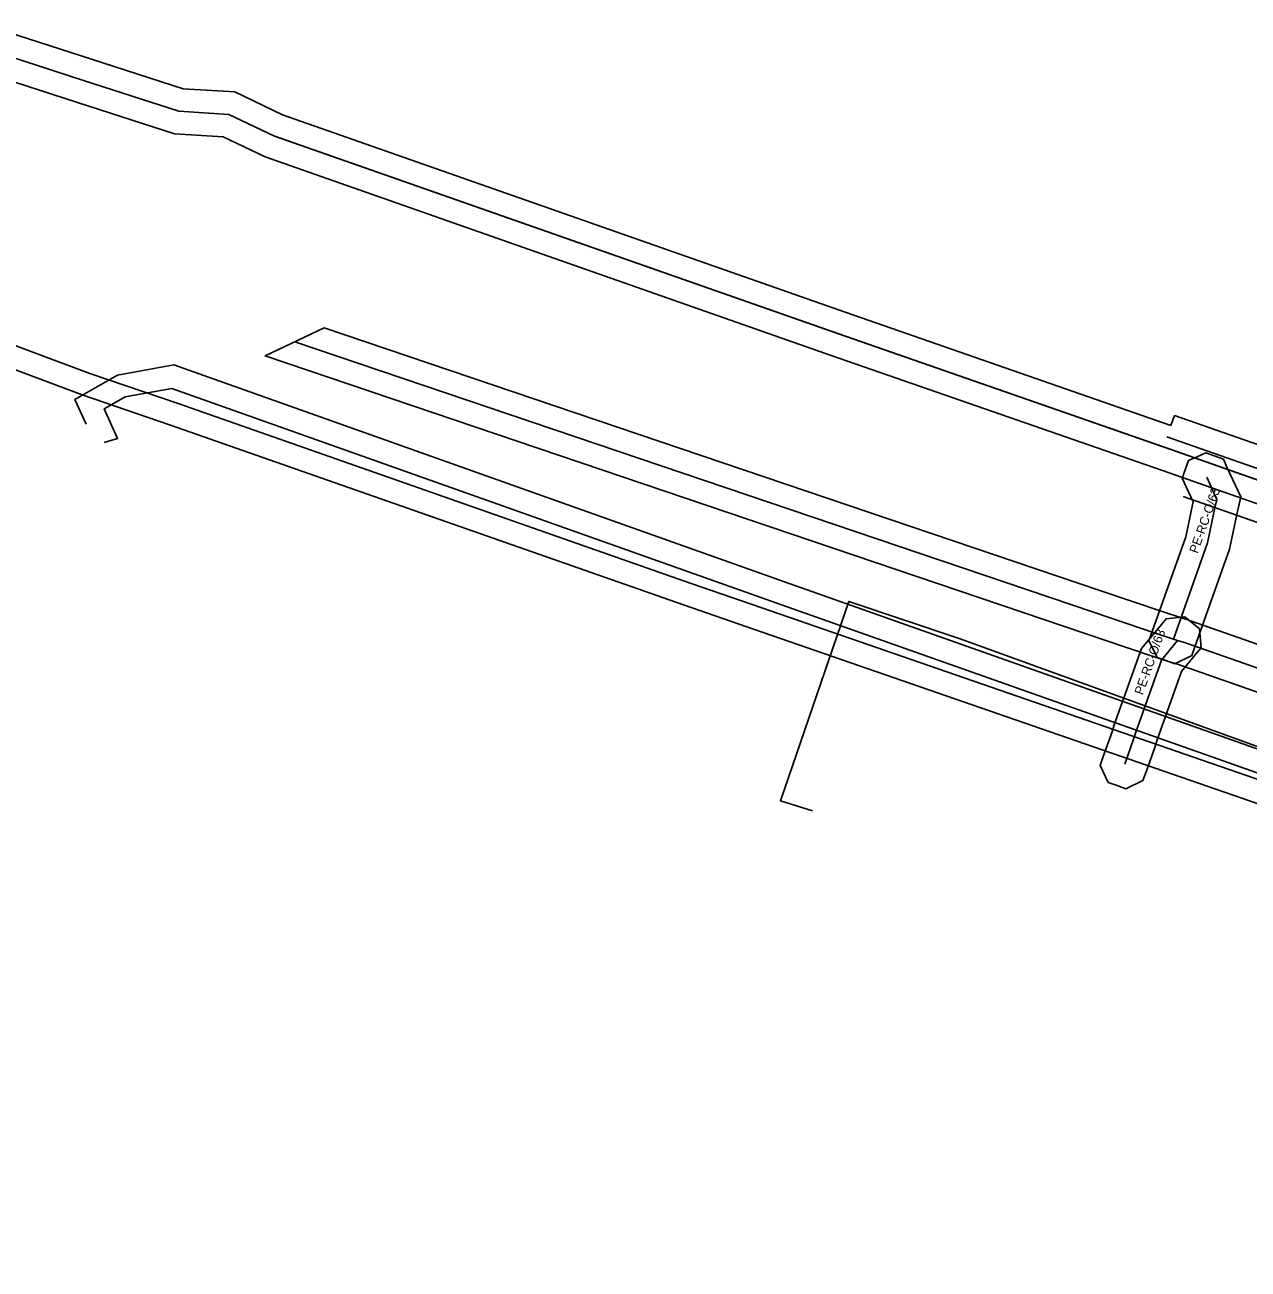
# Model space of a CAD drawing. Extents: x -762993 to -761845, y -975230 to -974501.
# Drawn here: x -762428 to -762374.2, y -974990.7 to -974935.9 of the extents above; entities that cross this region are included whole.
import ezdxf

# ---------------------------------------------------------------- set-up
doc = ezdxf.new("R2010")
doc.units = 0
for name, color, linetype in [('IS_CETIN_OP', 7, 'Continuous'), ('IS_CETIN_podzem NN', 7, 'Continuous'), ('IS_CETIN_podzem optika zam', 7, 'Continuous'), ('IS_CETIN_podzem out of order', 7, 'Continuous'), ('IS_CEZ-D_el vedeni NN podzem', 7, 'Continuous'), ('IS_CEZ-D_el vedeni VN podzem', 7, 'Continuous'), ('IS_CEZ-D_OP', 7, 'Continuous'), ('IS_CRA_OP', 7, 'Continuous'), ('IS_CRA_podzem telekomunikace', 7, 'Continuous'), ('IS_GASNET_plyn NTL anotace', 7, 'Continuous'), ('IS_GASNET_plyn NTL pripojky', 7, 'Continuous'), ('IS_GASNET_plyn NTL rad', 7, 'Continuous'), ('IS_GASNET_plyn OP', 7, 'Continuous')]:
    doc.layers.add(name, color=color, linetype=linetype)

msp = doc.modelspace()

# ---------------------------------------------------------------- linework, layer by layer
at = {"layer": 'IS_CETIN_OP'}
msp.add_line((-762377.43, -974953.086), (-762377.582, -974953.524), dxfattribs=at)
for points in [[(-762418.783, -974938.854), (-762416.677, -974939.865), (-762391.87, -974948.556), (-762377.582, -974953.524)], [(-762419.297, -974940.826), (-762417.443, -974941.715), (-762392.53, -974950.444), (-762377.95, -974955.514), (-762367.103, -974959.323), (-762363.702, -974960.533), (-762351.079, -974964.921), (-762349.293, -974965.589), (-762339.728, -974969), (-762336.376, -974970.461), (-762334.711, -974971.047)], [(-762377.43, -974953.086), (-762363.276, -974958.034), (-762359.216, -974959.394), (-762351.389, -974962.134)]]:
    msp.add_lwpolyline(points, dxfattribs=at)
at = {"layer": 'IS_CETIN_podzem NN'}
msp.add_lwpolyline([(-762377.76, -974954.03), (-762363.6, -974958.98), (-762359.54, -974960.34), (-762350.8, -974963.4)], dxfattribs=at)
at = {"layer": 'IS_CETIN_podzem optika zam'}
for points in [[(-762419.04, -974939.84), (-762417.06, -974940.79), (-762392.2, -974949.5), (-762377.62, -974954.57), (-762366.77, -974958.38)], [(-762377.76, -974954.03), (-762363.6, -974958.98), (-762359.54, -974960.34), (-762350.8, -974963.4)]]:
    msp.add_lwpolyline(points, dxfattribs=at)
at = {"layer": 'IS_CETIN_podzem out of order'}
for points in [[(-762377.04, -974956.66), (-762339.91, -974969.63), (-762327.23, -974974.06)], [(-762393.36, -974970.49), (-762394.76, -974970.05), (-762391.76, -974961.27), (-762386.9, -974962.9), (-762371.15, -974968.61), (-762342.91, -974978.3), (-762324.01, -974984.93), (-762322.43, -974985.48)]]:
    msp.add_lwpolyline(points, dxfattribs=at)
at = {"layer": 'IS_CEZ-D_el vedeni NN podzem'}
msp.add_lwpolyline([(-762424.533, -974954.278), (-762423.939, -974954.097), (-762424.533, -974952.804), (-762423.786, -974952.375), (-762423.603, -974952.27), (-762421.552, -974951.899), (-762394.922, -974961.348), (-762366.691, -974971.325)], dxfattribs=at)
at = {"layer": 'IS_CEZ-D_el vedeni VN podzem'}
msp.add_lwpolyline([(-762322.36, -974987.09), (-762324.59, -974986.24), (-762328.28, -974985.04), (-762360.05, -974973.9), (-762363.79, -974972.56), (-762395.59, -974961.56), (-762398.7, -974960.48), (-762421.28, -974952.57), (-762425.16, -974951.24), (-762434.97, -974947.57)], dxfattribs=at)
at = {"layer": 'IS_CEZ-D_OP'}
for points in [[(-762356.318, -974976.268), (-762360.384, -974974.843), (-762364.122, -974973.503), (-762395.917, -974962.505), (-762399.029, -974961.424), (-762421.607, -974953.515), (-762425.497, -974952.181), (-762435.253, -974948.532)], [(-762425.326, -974953.474), (-762425.823, -974952.392), (-762424.284, -974951.508), (-762423.951, -974951.317), (-762421.468, -974950.868), (-762394.588, -974960.405), (-762366.362, -974970.381), (-762338.599, -974979.92), (-762332.903, -974981.716), (-762317.463, -974987.706)]]:
    msp.add_lwpolyline(points, dxfattribs=at)
at = {"layer": 'IS_CRA_OP'}
for points in [[(-762425.086, -974937.412), (-762429.237, -974936.07), (-762432.173, -974935.904)], [(-762418.783, -974938.854), (-762421.055, -974938.71), (-762425.086, -974937.412)], [(-762425.7, -974939.316), (-762429.607, -974938.052), (-762432.285, -974937.9)], [(-762419.297, -974940.826), (-762421.43, -974940.691), (-762425.7, -974939.316)]]:
    msp.add_lwpolyline(points, dxfattribs=at)
at = {"layer": 'IS_CRA_podzem telekomunikace'}
for points in [[(-762425.393, -974938.364), (-762429.422, -974937.061), (-762432.23, -974936.902)], [(-762286.963, -974982.858), (-762286.915, -974983.05), (-762288.133, -974984.967), (-762290.685, -974986.061), (-762292.389, -974985.635), (-762300.689, -974982.775), (-762306.75, -974981.275), (-762318.851, -974976.949), (-762319.685, -974975.352), (-762321.623, -974974.461), (-762323.743, -974973.764), (-762326.285, -974972.953), (-762335.993, -974969.53), (-762339.363, -974968.07), (-762348.947, -974964.652), (-762363.377, -974959.593), (-762377.637, -974954.573), (-762392.217, -974949.493), (-762417.036, -974940.799), (-762419.044, -974939.84), (-762421.242, -974939.701), (-762425.393, -974938.364)]]:
    msp.add_lwpolyline(points, dxfattribs=at)
at = {"layer": 'IS_GASNET_plyn NTL pripojky'}
for points in [[(-762377.47, -974962.93), (-762375.97, -974958.7), (-762375.66, -974957.23), (-762375.56, -974956.78), (-762376.01, -974955.81)], [(-762377.29, -974962.99), (-762378, -974963.85), (-762379.13, -974967.03), (-762379.23, -974967.33), (-762379.62, -974968.43)]]:
    msp.add_lwpolyline(points, dxfattribs=at)
at = {"layer": 'IS_GASNET_plyn NTL rad'}
msp.add_lwpolyline([(-762416.145, -974949.855), (-762381.041, -974961.735), (-762378.19, -974962.7), (-762377.47, -974962.93), (-762377.29, -974962.99), (-762377.092, -974963.051), (-762377.03, -974963.07), (-762356.37, -974970.3), (-762354.158, -974971.062), (-762353.96, -974971.13), (-762350.61, -974972.23), (-762350.171, -974972.416), (-762350.02, -974972.48), (-762336.17, -974977.35), (-762335.29, -974977.64), (-762335.11, -974977.68), (-762305.627, -974988.849), (-762305.14, -974989.03), (-762304.73, -974989.2), (-762303.75, -974989.6), (-762303.207, -974990.005), (-762302.681, -974990.396), (-762302.34, -974990.65)], dxfattribs=at)
at = {"layer": 'IS_GASNET_plyn OP'}
msp.add_lwpolyline([(-762356.698, -974971.245), (-762377.342, -974964.02), (-762377.386, -974964.007), (-762377.595, -974963.942), (-762377.78, -974963.881), (-762378.502, -974963.65), (-762381.362, -974962.682), (-762417.443, -974950.472), (-762414.847, -974949.239), (-762380.72, -974960.788), (-762377.878, -974961.75), (-762377.16, -974961.979), (-762376.985, -974962.038), (-762376.798, -974962.095), (-762376.718, -974962.12), (-762356.042, -974969.355)], dxfattribs=at)
for points in [[(-762378.551, -974962.986), (-762378.412, -974962.596), (-762376.935, -974958.429), (-762376.637, -974957.018), (-762376.61, -974956.894), (-762376.917, -974956.231), (-762377.091, -974955.855), (-762376.807, -974955.077), (-762376.431, -974954.903), (-762376.055, -974954.729), (-762375.277, -974955.013), (-762375.103, -974955.389), (-762374.51, -974956.666), (-762374.683, -974957.442), (-762375.005, -974958.971), (-762376.528, -974963.264), (-762376.666, -974963.655), (-762377.414, -974964.011), (-762377.804, -974963.872), (-762378.195, -974963.734)], [(-762376.255, -974963.307), (-762376.519, -974963.627), (-762377.117, -974964.351), (-762378.184, -974967.356), (-762378.284, -974967.655), (-762378.677, -974968.764), (-762378.816, -974969.155), (-762379.564, -974969.511), (-762379.954, -974969.373), (-762380.345, -974969.234), (-762380.701, -974968.486), (-762380.563, -974968.096), (-762380.176, -974967.005), (-762380.076, -974966.704), (-762378.883, -974963.349), (-762378.061, -974962.353), (-762377.798, -974962.034), (-762376.973, -974961.955), (-762376.653, -974962.219), (-762376.334, -974962.482)]]:
    msp.add_lwpolyline(points, close=True, dxfattribs=at)

# ---------------------------------------------------------------- texts
at = {"layer": 'IS_GASNET_plyn NTL anotace'}
for rotation, p in [(70.475, (-762376.413, -974959.186)), (70.4375, (-762378.827, -974965.413))]:
    msp.add_text('PE-RC-O/63', height=0.4, rotation=rotation, dxfattribs=at).set_placement(p)

doc.saveas('drawing.dxf')
